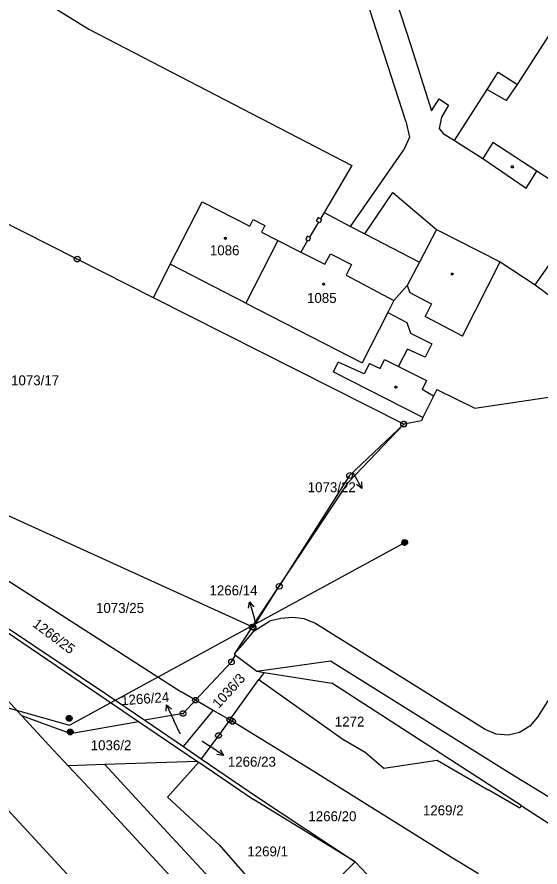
# Model space of a CAD drawing. Extents: x -806774 to -803680, y -1151731 to -1150053.
# Drawn here: x -804204.1 to -804114.6, y -1150506.7 to -1150361.4 of the extents above; entities that cross this region are included whole.
import ezdxf

# ---------------------------------------------------------------- set-up
doc = ezdxf.new("R2010")
doc.units = 0
for name, color, linetype in [('1', 7, 'Continuous'), ('12', 7, 'Continuous'), ('2', 7, 'Continuous'), ('4', 7, 'Continuous'), ('5', 7, 'Continuous'), ('6', 7, 'Continuous'), ('7', 7, 'Continuous'), ('8', 7, 'Continuous')]:
    doc.layers.add(name, color=color, linetype=linetype)

msp = doc.modelspace()

# ---------------------------------------------------------------- linework, layer by layer
at = {"layer": '1'}
for p, q in [((-804153.67, -1150314.5), (-804136.72, -1150366.3)), ((-804137.59, -1150379.24), (-804148.11, -1150346.67)), ((-804199.97, -1150358.37), (-804191.79, -1150363.51)), ((-804191.79, -1150363.51), (-804146.78, -1150386.81)), ((-804118.45, -1150372.97), (-804111.88, -1150362.71)), ((-804136.72, -1150366.3), (-804133.18, -1150377.45)), ((-804123.67, -1150373.78), (-804121.79, -1150370.84)), ((-804121.79, -1150370.84), (-804118.45, -1150372.97)), ((-804129.25, -1150382.55), (-804123.67, -1150373.78)), ((-804133.18, -1150377.45), (-804131.86, -1150375.39)), ((-804131.86, -1150375.39), (-804130.27, -1150376.47)), ((-804130.27, -1150376.47), (-804131.45, -1150378.51)), ((-804131.45, -1150378.51), (-804131.86, -1150380.48)), ((-804137.59, -1150379.24), (-804136.94, -1150381.98)), ((-804131.86, -1150380.48), (-804131.18, -1150381.33)), ((-804131.18, -1150381.33), (-804129.25, -1150382.55)), ((-804136.94, -1150381.98), (-804137.9, -1150384.11)), ((-804129.25, -1150382.55), (-804124.41, -1150385.63)), ((-804147.02, -1150397.2), (-804137.9, -1150384.11)), ((-804124.41, -1150385.63), (-804117.01, -1150390.65)), ((-804146.78, -1150386.81), (-804151.55, -1150394.86)), ((-804117.01, -1150390.65), (-804115.18, -1150387.77)), ((-804086.74, -1150406.28), (-804115.18, -1150387.77)), ((-804144.57, -1150398.47), (-804139.79, -1150391.42)), ((-804139.79, -1150391.42), (-804132.31, -1150397.71)), ((-804177.86, -1150403.69), (-804172.43, -1150392.98)), ((-804172.43, -1150392.98), (-804164.24, -1150397.15)), ((-804193.78, -1150402.81), (-804211.44, -1150393.91)), ((-804164.24, -1150397.15), (-804163.68, -1150396.04)), ((-804163.68, -1150396.04), (-804161.69, -1150397.06)), ((-804151.55, -1150394.86), (-804152.19, -1150395.94)), ((-804152.19, -1150395.94), (-804151.98, -1150396.07)), ((-804151.55, -1150394.86), (-804147.02, -1150397.2)), ((-804161.69, -1150397.06), (-804162.26, -1150398.17)), ((-804152.5, -1150396.47), (-804154.04, -1150399.07)), ((-804152.29, -1150396.59), (-804152.5, -1150396.47)), ((-804151.98, -1150396.07), (-804152.29, -1150396.59)), ((-804147.02, -1150397.2), (-804146.7, -1150397.37)), ((-804146.7, -1150397.37), (-804144.92, -1150398.29)), ((-804162.26, -1150398.17), (-804159.47, -1150399.59)), ((-804144.92, -1150398.29), (-804144.57, -1150398.47)), ((-804132.31, -1150397.71), (-804135.23, -1150403.3)), ((-804132.31, -1150397.71), (-804121.43, -1150403.27)), ((-804159.47, -1150399.59), (-804164.91, -1150410.32)), ((-804159.47, -1150399.59), (-804155.53, -1150401.6)), ((-804154.37, -1150399.62), (-804155.53, -1150401.6)), ((-804154.16, -1150399.75), (-804154.37, -1150399.62)), ((-804153.86, -1150399.22), (-804154.16, -1150399.75)), ((-804154.04, -1150399.07), (-804153.86, -1150399.22)), ((-804115.43, -1150407.21), (-804110.61, -1150400.26)), ((-804180.75, -1150409.39), (-804193.78, -1150402.81)), ((-804135.23, -1150403.3), (-804137.34, -1150407.33)), ((-804121.43, -1150403.27), (-804115.43, -1150407.21)), ((-804180.75, -1150409.39), (-804177.86, -1150403.69)), ((-804164.91, -1150410.32), (-804177.86, -1150403.69)), ((-804137.34, -1150407.33), (-804139.6, -1150409.87)), ((-804137.94, -1150431.01), (-804180.75, -1150409.39)), ((-804164.91, -1150410.32), (-804145.02, -1150420.5)), ((-804139.6, -1150409.87), (-804140.65, -1150411.94)), ((-804140.65, -1150411.94), (-804145.02, -1150420.5)), ((-804125.76, -1150428.3), (-804096.4, -1150423.85)), ((-804132.85, -1150426.25), (-804134.64, -1150429.88)), ((-804132.29, -1150425.11), (-804132.85, -1150426.25)), ((-804132.29, -1150425.11), (-804125.76, -1150428.3)), ((-804134.91, -1150430.45), (-804137.94, -1150431.01)), ((-804134.64, -1150429.88), (-804134.91, -1150430.45)), ((-804147.38, -1150440.94), (-804137.94, -1150431.01)), ((-804137.94, -1150431.01), (-804147.18, -1150439.79)), ((-804147.18, -1150439.79), (-804159.21, -1150458.72)), ((-804159.21, -1150458.72), (-804147.38, -1150440.94)), ((-804163.83, -1150465.67), (-804208.87, -1150445.2)), ((-804213.63, -1150452.62), (-804176.02, -1150476.77)), ((-804217.33, -1150458.04), (-804188.61, -1150477.27)), ((-804217.68, -1150458.55), (-804183.31, -1150481.83)), ((-804163.83, -1150465.67), (-804159.21, -1150458.72)), ((-804163.67, -1150465.74), (-804159.21, -1150458.72)), ((-804158.95, -1150464.21), (-804160.91, -1150464.71)), ((-804156.95, -1150464.08), (-804158.95, -1150464.21)), ((-804154.98, -1150464.3), (-804156.95, -1150464.08)), ((-804153.13, -1150465.01), (-804154.98, -1150464.3)), ((-804163.83, -1150465.67), (-804166.94, -1150470.34)), ((-804163.83, -1150465.67), (-804163.67, -1150465.74)), ((-804163.52, -1150466.35), (-804160.91, -1150464.71)), ((-804123.99, -1150483.22), (-804153.13, -1150465.01)), ((-804165.58, -1150468.76), (-804163.52, -1150466.35)), ((-804165.58, -1150468.76), (-804166.94, -1150470.34)), ((-804167.38, -1150471.65), (-804166.7, -1150470.52)), ((-804166.94, -1150470.34), (-804166.7, -1150470.52)), ((-804166.7, -1150470.52), (-804163.07, -1150473.24)), ((-804163.07, -1150473.24), (-804150.44, -1150471.47)), ((-804150.44, -1150471.47), (-804119.72, -1150490.69)), ((-804173.54, -1150478.2), (-804167.38, -1150471.65)), ((-804109.79, -1150472.7), (-804115.05, -1150481.07)), ((-804163.07, -1150473.24), (-804161.82, -1150473.44)), ((-804161.82, -1150473.44), (-804162.71, -1150474.67)), ((-804161.82, -1150473.44), (-804150.25, -1150475.3)), ((-804167.68, -1150481.57), (-804162.71, -1150474.67)), ((-804162.71, -1150474.67), (-804148.37, -1150484.88)), ((-804117.84, -1150496.2), (-804150.25, -1150475.3)), ((-804207.15, -1150476.64), (-804203.22, -1150480.89)), ((-804188.61, -1150477.27), (-804182.21, -1150481.63)), ((-804173.54, -1150478.2), (-804176.02, -1150476.77)), ((-804173.54, -1150478.2), (-804175.68, -1150480.47)), ((-804170.52, -1150479.94), (-804173.54, -1150478.2)), ((-804175.62, -1150486.13), (-804170.52, -1150479.94)), ((-804167.68, -1150481.57), (-804170.52, -1150479.94)), ((-804194.96, -1150483.87), (-804203.22, -1150480.89)), ((-804203.22, -1150480.89), (-804197.86, -1150486.67)), ((-804175.68, -1150480.47), (-804182.21, -1150481.63)), ((-804182.21, -1150481.63), (-804175.62, -1150486.13)), ((-804167.68, -1150481.57), (-804169.6, -1150484.24)), ((-804167.68, -1150481.57), (-804167.22, -1150481.83)), ((-804115.05, -1150481.07), (-804116.39, -1150482.61)), ((-804194.96, -1150483.87), (-804183.31, -1150481.83)), ((-804183.31, -1150481.83), (-804173.19, -1150488.68)), ((-804154.07, -1150489.93), (-804167.22, -1150481.83)), ((-804122.11, -1150484.02), (-804123.99, -1150483.22)), ((-804116.39, -1150482.61), (-804118.11, -1150483.74)), ((-804169.6, -1150484.24), (-804172.55, -1150488.22)), ((-804120.09, -1150484.19), (-804122.11, -1150484.02)), ((-804118.11, -1150483.74), (-804120.09, -1150484.19)), ((-804148.37, -1150484.88), (-804144.54, -1150487.07)), ((-804197.86, -1150486.67), (-804195.32, -1150489.41)), ((-804175.62, -1150486.13), (-804172.55, -1150488.22)), ((-804144.54, -1150487.07), (-804141.31, -1150489.79)), ((-804173.19, -1150488.68), (-804189.03, -1150489.2)), ((-804172.99, -1150488.81), (-804178.35, -1150494.75)), ((-804173.19, -1150488.68), (-804172.99, -1150488.81)), ((-804172.99, -1150488.81), (-804163.62, -1150495.16)), ((-804172.55, -1150488.22), (-804163.09, -1150494.68)), ((-804141.31, -1150489.79), (-804132.2, -1150488.43)), ((-804132.2, -1150488.43), (-804123.35, -1150493.57)), ((-804189.03, -1150489.2), (-804195.32, -1150489.41)), ((-804195.32, -1150489.41), (-804192.55, -1150492.4)), ((-804189.03, -1150489.2), (-804181.12, -1150497.76)), ((-804129.95, -1150504.97), (-804154.07, -1150489.93)), ((-804119.72, -1150490.69), (-804100.25, -1150502.6)), ((-804192.55, -1150492.4), (-804170.14, -1150516.6)), ((-804169.49, -1150502.94), (-804178.35, -1150494.75)), ((-804163.09, -1150494.68), (-804146.22, -1150505.84)), ((-804118.09, -1150496.67), (-804123.35, -1150493.57)), ((-804206.45, -1150496.09), (-804175.77, -1150529.26)), ((-804146.22, -1150505.84), (-804163.62, -1150495.16)), ((-804117.84, -1150496.2), (-804118.09, -1150496.67)), ((-804117.84, -1150496.2), (-804106.86, -1150503.28)), ((-804181.12, -1150497.76), (-804142.6, -1150539.45)), ((-804169.49, -1150502.94), (-804139.75, -1150536.68)), ((-804125.16, -1150507.9), (-804129.95, -1150504.97)), ((-804150, -1150509.6), (-804146.22, -1150505.84)), ((-804133.38, -1150519.26), (-804146.22, -1150505.84))]:
    msp.add_line(p, q, dxfattribs=at)
at = {"layer": '12'}
for p, q in [((-804118.45, -1150372.97), (-804111.88, -1150362.71)), ((-804129.25, -1150382.55), (-804123.67, -1150373.78)), ((-804123.67, -1150373.78), (-804120.36, -1150375.68)), ((-804120.36, -1150375.68), (-804118.45, -1150372.97)), ((-804129.25, -1150382.55), (-804124.41, -1150385.63)), ((-804122.71, -1150382.87), (-804124.41, -1150385.63)), ((-804115.18, -1150387.77), (-804122.71, -1150382.87)), ((-804086.74, -1150406.28), (-804115.18, -1150387.77)), ((-804177.86, -1150403.69), (-804172.43, -1150392.98)), ((-804172.43, -1150392.98), (-804164.24, -1150397.15)), ((-804164.24, -1150397.15), (-804163.68, -1150396.04)), ((-804163.68, -1150396.04), (-804161.69, -1150397.06)), ((-804161.69, -1150397.06), (-804162.26, -1150398.17)), ((-804162.26, -1150398.17), (-804159.47, -1150399.59)), ((-804159.47, -1150399.59), (-804164.91, -1150410.32)), ((-804159.47, -1150399.59), (-804164.91, -1150410.32)), ((-804159.47, -1150399.59), (-804155.53, -1150401.6)), ((-804155.53, -1150401.6), (-804151.4, -1150403.68)), ((-804151.4, -1150403.68), (-804150.46, -1150401.87)), ((-804150.46, -1150401.87), (-804146.87, -1150403.71)), ((-804164.91, -1150410.32), (-804177.86, -1150403.69)), ((-804146.87, -1150403.71), (-804147.78, -1150405.55)), ((-804147.78, -1150405.55), (-804139.6, -1150409.87)), ((-804164.91, -1150410.32), (-804145.02, -1150420.5)), ((-804139.6, -1150409.87), (-804140.65, -1150411.94)), ((-804140.65, -1150411.94), (-804145.02, -1150420.5)), ((-804207.15, -1150476.64), (-804203.22, -1150480.89)), ((-804203.22, -1150480.89), (-804197.86, -1150486.67)), ((-804197.86, -1150486.67), (-804195.32, -1150489.41)), ((-804195.32, -1150489.41), (-804192.55, -1150492.4)), ((-804192.55, -1150492.4), (-804170.14, -1150516.6)), ((-804206.45, -1150496.09), (-804175.77, -1150529.26))]:
    msp.add_line(p, q, dxfattribs=at)
at = {"layer": '4'}
for p, q in [((-804123.67, -1150373.78), (-804120.36, -1150375.68)), ((-804120.36, -1150375.68), (-804118.45, -1150372.97)), ((-804122.71, -1150382.87), (-804124.41, -1150385.63)), ((-804115.18, -1150387.77), (-804122.71, -1150382.87)), ((-804152.55, -1150395.69), (-804152.88, -1150396.27)), ((-804152.19, -1150395.94), (-804152.55, -1150395.69)), ((-804152.88, -1150396.27), (-804152.5, -1150396.47)), ((-804154.42, -1150398.9), (-804154.7, -1150399.44)), ((-804154.04, -1150399.07), (-804154.42, -1150398.9)), ((-804144.57, -1150398.47), (-804135.23, -1150403.3)), ((-804154.7, -1150399.44), (-804154.37, -1150399.62)), ((-804155.53, -1150401.6), (-804151.4, -1150403.68)), ((-804151.4, -1150403.68), (-804150.46, -1150401.87)), ((-804150.46, -1150401.87), (-804146.87, -1150403.71)), ((-804127.89, -1150415.99), (-804121.43, -1150403.27)), ((-804146.87, -1150403.71), (-804147.78, -1150405.55)), ((-804147.78, -1150405.55), (-804139.6, -1150409.87)), ((-804137.34, -1150407.33), (-804136.88, -1150408.49)), ((-804115.43, -1150407.21), (-804110.84, -1150410.62)), ((-804136.88, -1150408.49), (-804134.07, -1150409.99)), ((-804133.21, -1150410.45), (-804134.29, -1150412.62)), ((-804134.07, -1150409.99), (-804133.21, -1150410.45)), ((-804140.65, -1150411.94), (-804137.39, -1150413.66)), ((-804127.89, -1150415.99), (-804134.29, -1150412.62)), ((-804137.39, -1150413.66), (-804136.79, -1150415.45)), ((-804136.79, -1150415.45), (-804133.15, -1150417.27)), ((-804133.15, -1150417.27), (-804134.29, -1150419.55)), ((-804138.82, -1150421.14), (-804137.29, -1150418.2)), ((-804134.29, -1150419.55), (-804137.29, -1150418.2)), ((-804149.14, -1150420.41), (-804150.01, -1150422.09)), ((-804144.68, -1150422.39), (-804149.14, -1150420.41)), ((-804143.77, -1150420.64), (-804144.68, -1150422.39)), ((-804143.77, -1150420.64), (-804141.98, -1150421.49)), ((-804141.98, -1150421.49), (-804141.2, -1150419.94)), ((-804141.2, -1150419.94), (-804138.82, -1150421.14)), ((-804134.64, -1150429.88), (-804150.01, -1150422.09)), ((-804138.82, -1150421.14), (-804134.03, -1150423.54)), ((-804134.03, -1150423.54), (-804134.79, -1150425.06)), ((-804132.85, -1150426.25), (-804134.79, -1150425.06))]:
    msp.add_line(p, q, dxfattribs=at)
at = {"layer": '5'}
for points in [[(-804119.26, -1150386.88), (-804119.17, -1150387.03), (-804119.26, -1150387.18), (-804119.44, -1150387.18), (-804119.53, -1150387.03), (-804119.44, -1150386.88)], [(-804168.44, -1150399.08), (-804168.34, -1150399.1), (-804168.29, -1150399.19), (-804168.27, -1150399.25), (-804168.29, -1150399.34), (-804168.37, -1150399.41), (-804168.44, -1150399.42), (-804168.53, -1150399.39), (-804168.59, -1150399.33), (-804168.61, -1150399.25), (-804168.59, -1150399.16), (-804168.51, -1150399.09)], [(-804129.55, -1150405.18), (-804129.46, -1150405.33), (-804129.55, -1150405.48), (-804129.73, -1150405.48), (-804129.82, -1150405.33), (-804129.73, -1150405.18)], [(-804151.63, -1150406.9), (-804151.53, -1150406.92), (-804151.48, -1150407.01), (-804151.46, -1150407.07), (-804151.48, -1150407.16), (-804151.56, -1150407.23), (-804151.63, -1150407.24), (-804151.72, -1150407.21), (-804151.78, -1150407.15), (-804151.8, -1150407.07), (-804151.78, -1150406.98), (-804151.7, -1150406.91)], [(-804139.19, -1150424.54), (-804139.1, -1150424.69), (-804139.19, -1150424.84), (-804139.37, -1150424.84), (-804139.46, -1150424.69), (-804139.37, -1150424.54)]]:
    msp.add_lwpolyline(points, close=True, dxfattribs=at)
at = {"layer": '6'}
for p, q in [((-804195.07, -1150482.47), (-804137.75, -1150451.24)), ((-804265.77, -1150462.58), (-804195.07, -1150482.47))]:
    msp.add_line(p, q, dxfattribs=at)
for points in [[(-804138.24, -1150451.36), (-804138.22, -1150451.05), (-804138.02, -1150450.81), (-804137.73, -1150450.73), (-804137.44, -1150450.85), (-804137.28, -1150451.11), (-804137.3, -1150451.42), (-804137.5, -1150451.66), (-804137.79, -1150451.74), (-804138.07, -1150451.62), (-804138.24, -1150451.36), (-804138.2, -1150451.33), (-804138.18, -1150451.09), (-804138.09, -1150450.94), (-804138.13, -1150451.5), (-804138.05, -1150451.58), (-804138.01, -1150450.86), (-804137.93, -1150450.87), (-804137.97, -1150451.59), (-804137.89, -1150451.63), (-804137.84, -1150450.83), (-804137.76, -1150450.8), (-804137.82, -1150451.68), (-804137.74, -1150451.68), (-804137.68, -1150450.8), (-804137.6, -1150450.84), (-804137.66, -1150451.65), (-804137.57, -1150451.64), (-804137.52, -1150450.83), (-804137.45, -1150450.89), (-804137.49, -1150451.61), (-804137.41, -1150451.53), (-804137.37, -1150450.97), (-804137.3, -1150451.09), (-804137.32, -1150451.43)], [(-804195.3, -1150480.82), (-804194.99, -1150480.82), (-804194.74, -1150481), (-804194.64, -1150481.29), (-804194.74, -1150481.58), (-804194.99, -1150481.76), (-804195.3, -1150481.76), (-804195.55, -1150481.58), (-804195.65, -1150481.29), (-804195.55, -1150481), (-804195.3, -1150480.82), (-804195.27, -1150480.86), (-804195.03, -1150480.86), (-804194.87, -1150480.94), (-804195.43, -1150480.94), (-804195.51, -1150481.02), (-804194.79, -1150481.02), (-804194.79, -1150481.1), (-804195.51, -1150481.1), (-804195.55, -1150481.18), (-804194.75, -1150481.18), (-804194.71, -1150481.26), (-804195.59, -1150481.26), (-804195.59, -1150481.34), (-804194.71, -1150481.34), (-804194.74, -1150481.42), (-804195.55, -1150481.42), (-804195.54, -1150481.5), (-804194.73, -1150481.5), (-804194.78, -1150481.58), (-804195.5, -1150481.58), (-804195.42, -1150481.66), (-804194.86, -1150481.66), (-804194.97, -1150481.74), (-804195.31, -1150481.74)], [(-804195.14, -1150483.15), (-804194.83, -1150483.15), (-804194.58, -1150483.33), (-804194.48, -1150483.62), (-804194.58, -1150483.91), (-804194.83, -1150484.09), (-804195.14, -1150484.09), (-804195.39, -1150483.91), (-804195.49, -1150483.62), (-804195.39, -1150483.33), (-804195.14, -1150483.15), (-804195.11, -1150483.19), (-804194.87, -1150483.19), (-804194.71, -1150483.27), (-804195.27, -1150483.27), (-804195.35, -1150483.35), (-804194.63, -1150483.35), (-804194.63, -1150483.43), (-804195.35, -1150483.43), (-804195.39, -1150483.51), (-804194.59, -1150483.51), (-804194.55, -1150483.59), (-804195.43, -1150483.59), (-804195.43, -1150483.67), (-804194.55, -1150483.67), (-804194.58, -1150483.75), (-804195.39, -1150483.75), (-804195.38, -1150483.83), (-804194.57, -1150483.83), (-804194.62, -1150483.91), (-804195.34, -1150483.91), (-804195.26, -1150483.99), (-804194.7, -1150483.99), (-804194.81, -1150484.07), (-804195.15, -1150484.07)]]:
    msp.add_lwpolyline(points, dxfattribs=at)
at = {"layer": '7'}
for p, q in [((-804145.1, -1150441.98), (-804146.55, -1150439.36)), ((-804164.31, -1150461.39), (-804163.46, -1150464.27)), ((-804163.26, -1150464.96), (-804163.46, -1150464.27)), ((-804178.52, -1150478.97), (-804177.24, -1150481.68)), ((-804176.17, -1150483.96), (-804177.24, -1150481.68)), ((-804172.33, -1150485.22), (-804171.25, -1150485.95)), ((-804168.77, -1150487.63), (-804171.25, -1150485.95))]:
    msp.add_line(p, q, dxfattribs=at)
for points in [[(-804145.14, -1150440.87), (-804145.1, -1150441.98), (-804146.02, -1150441.35)], [(-804164.5, -1150462.49), (-804164.31, -1150461.39), (-804163.54, -1150462.21)], [(-804178.54, -1150480.08), (-804178.52, -1150478.97), (-804177.64, -1150479.66)], [(-804169.31, -1150486.66), (-804168.77, -1150487.63), (-804169.87, -1150487.49)]]:
    msp.add_lwpolyline(points, dxfattribs=at)
at = {"layer": '8'}
for p, q in [((-804193.9, -1150402.82), (-804193.66, -1150402.8)), ((-804137.95, -1150431.13), (-804137.93, -1150430.89)), ((-804138.06, -1150431.02), (-804137.82, -1150431)), ((-804147.19, -1150439.91), (-804147.17, -1150439.67)), ((-804159.22, -1150458.84), (-804159.2, -1150458.6)), ((-804163.84, -1150465.79), (-804163.82, -1150465.55)), ((-804163.68, -1150465.86), (-804163.66, -1150465.62)), ((-804167.39, -1150471.77), (-804167.37, -1150471.53)), ((-804173.66, -1150478.2), (-804173.42, -1150478.2)), ((-804175.8, -1150480.47), (-804175.56, -1150480.47)), ((-804167.8, -1150481.57), (-804167.56, -1150481.57)), ((-804167.34, -1150481.83), (-804167.1, -1150481.83)), ((-804169.72, -1150484.24), (-804169.48, -1150484.24))]:
    msp.add_line(p, q, dxfattribs=at)
for points in [[(-804193.65, -1150402.32), (-804193.39, -1150402.49), (-804193.28, -1150402.78), (-804193.37, -1150403.07), (-804193.61, -1150403.26), (-804193.92, -1150403.28), (-804194.18, -1150403.11), (-804194.29, -1150402.82), (-804194.2, -1150402.53), (-804193.96, -1150402.34)], [(-804137.81, -1150430.52), (-804137.55, -1150430.69), (-804137.44, -1150430.98), (-804137.53, -1150431.27), (-804137.77, -1150431.46), (-804138.08, -1150431.48), (-804138.34, -1150431.31), (-804138.45, -1150431.02), (-804138.36, -1150430.73), (-804138.12, -1150430.54)], [(-804138.41, -1150430.83), (-804138.21, -1150430.59), (-804137.92, -1150430.51), (-804137.64, -1150430.63), (-804137.47, -1150430.89), (-804137.49, -1150431.2), (-804137.69, -1150431.44), (-804137.98, -1150431.52), (-804138.27, -1150431.4), (-804138.43, -1150431.14)], [(-804147.65, -1150439.61), (-804147.45, -1150439.37), (-804147.16, -1150439.29), (-804146.88, -1150439.41), (-804146.71, -1150439.67), (-804146.73, -1150439.98), (-804146.93, -1150440.22), (-804147.22, -1150440.3), (-804147.51, -1150440.18), (-804147.67, -1150439.92)], [(-804159.68, -1150458.54), (-804159.48, -1150458.3), (-804159.19, -1150458.22), (-804158.91, -1150458.34), (-804158.74, -1150458.6), (-804158.76, -1150458.91), (-804158.96, -1150459.15), (-804159.25, -1150459.23), (-804159.54, -1150459.11), (-804159.7, -1150458.85)], [(-804164.3, -1150465.49), (-804164.1, -1150465.25), (-804163.81, -1150465.17), (-804163.53, -1150465.29), (-804163.36, -1150465.55), (-804163.38, -1150465.86), (-804163.58, -1150466.1), (-804163.87, -1150466.18), (-804164.16, -1150466.06), (-804164.32, -1150465.8)], [(-804164.14, -1150465.56), (-804163.94, -1150465.32), (-804163.65, -1150465.24), (-804163.37, -1150465.36), (-804163.2, -1150465.62), (-804163.22, -1150465.93), (-804163.42, -1150466.17), (-804163.71, -1150466.25), (-804164, -1150466.13), (-804164.16, -1150465.87)], [(-804167.85, -1150471.47), (-804167.65, -1150471.23), (-804167.36, -1150471.15), (-804167.08, -1150471.27), (-804166.91, -1150471.53), (-804166.93, -1150471.84), (-804167.13, -1150472.08), (-804167.42, -1150472.16), (-804167.71, -1150472.04), (-804167.87, -1150471.78)], [(-804173.39, -1150477.72), (-804173.14, -1150477.9), (-804173.04, -1150478.19), (-804173.14, -1150478.48), (-804173.39, -1150478.66), (-804173.7, -1150478.66), (-804173.95, -1150478.48), (-804174.05, -1150478.19), (-804173.95, -1150477.9), (-804173.7, -1150477.72)], [(-804175.53, -1150479.99), (-804175.28, -1150480.17), (-804175.18, -1150480.46), (-804175.28, -1150480.75), (-804175.53, -1150480.93), (-804175.84, -1150480.93), (-804176.09, -1150480.75), (-804176.19, -1150480.46), (-804176.09, -1150480.17), (-804175.84, -1150479.99)], [(-804167.53, -1150481.09), (-804167.28, -1150481.27), (-804167.18, -1150481.56), (-804167.28, -1150481.85), (-804167.53, -1150482.03), (-804167.84, -1150482.03), (-804168.09, -1150481.85), (-804168.19, -1150481.56), (-804168.09, -1150481.27), (-804167.84, -1150481.09)], [(-804167.07, -1150481.35), (-804166.82, -1150481.53), (-804166.72, -1150481.82), (-804166.82, -1150482.11), (-804167.07, -1150482.29), (-804167.38, -1150482.29), (-804167.63, -1150482.11), (-804167.73, -1150481.82), (-804167.63, -1150481.53), (-804167.38, -1150481.35)], [(-804169.45, -1150483.76), (-804169.2, -1150483.94), (-804169.1, -1150484.23), (-804169.2, -1150484.52), (-804169.45, -1150484.7), (-804169.76, -1150484.7), (-804170.01, -1150484.52), (-804170.11, -1150484.23), (-804170.01, -1150483.94), (-804169.76, -1150483.76)]]:
    msp.add_lwpolyline(points, close=True, dxfattribs=at)

# ---------------------------------------------------------------- texts
at = {"layer": '2'}
for s, height, p in [('1086', 1.7, (-804171.08, -1150402.14)), ('1085', 1.7, (-804154.47, -1150410.29)), ('1073/17', 1.7, (-804205.08, -1150424.37)), ('1073/22', 0.1, (-804146.53, -1150439.36)), ('1073/25', 1.7, (-804190.56, -1150463.28)), ('1266/14', 0.1, (-804163.24, -1150464.96)), ('1272', 1.7, (-804149.72, -1150482.7)), ('1036/2', 1.7, (-804191.46, -1150486.74)), ('1269/2', 1.7, (-804134.65, -1150497.87)), ('1266/20', 1.7, (-804154.24, -1150498.88)), ('1269/1', 1.7, (-804164.68, -1150504.89))]:
    msp.add_text(s, height=height, dxfattribs=at).set_placement(p)
for s, height, rotation, p in [('1266/25', 1.7, 323.0909, (-804201.54, -1150465.47)), ('1036/3', 1.7, 47.7274, (-804169.58, -1150479.71)), ('1266/24', 0.1, 32.0283, (-804176.4, -1150484.1)), ('1266/23', 0.1, 51.91, (-804172.5, -1150485.44))]:
    msp.add_text(s, height=height, rotation=rotation, dxfattribs=at).set_placement(p)
at = {"layer": '7'}
for s, p in [('1073/22', (-804154.35, -1150442.64)), ('1266/14', (-804171.15, -1150460.27)), ('1266/23', (-804168.01, -1150489.56))]:
    msp.add_text(s, height=1.7, dxfattribs=at).set_placement(p)
msp.add_text('1266/24', height=1.7, rotation=4.1253, dxfattribs=at).set_placement((-804186.19, -1150479.07))

doc.saveas('drawing.dxf')
